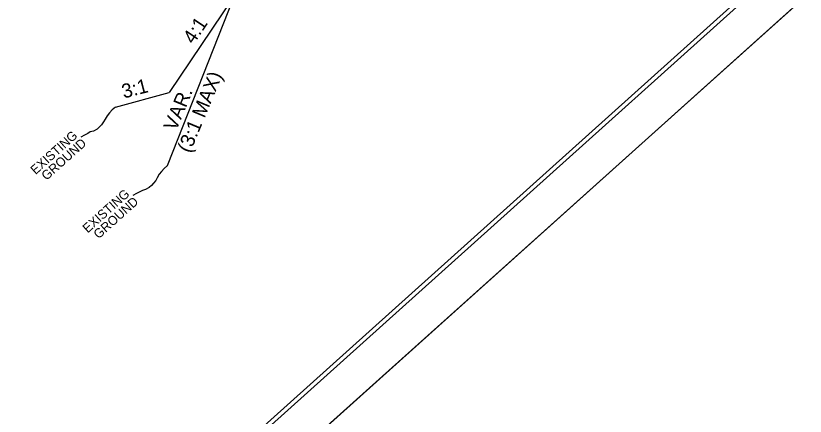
# Model space of a CAD drawing. Extents: x 2488411 to 2488707, y 383669 to 383962.
# Drawn here: x 2488587.3 to 2488643.1, y 383775.9 to 383804.2 of the extents above; entities that cross this region are included whole.
import ezdxf

# ---------------------------------------------------------------- set-up
doc = ezdxf.new("R2010")
doc.units = 0
for name, color, linetype in [('Old_Level_19', 7, 'Continuous'), ('Old_Level_21', 7, 'Continuous'), ('Prop Roadway Profile Bench Mark Info Text', 7, 'Continuous'), ('Prop XS SE Text', 7, 'Continuous'), ('Sheet Cutting Line CELL', 7, 'Continuous'), ('Sheet Plan CELL', 7, 'Continuous'), ('Sheet Title CELL', 7, 'Continuous'), ('Typical Text ID Circle CELL', 7, 'Continuous')]:
    doc.layers.add(name, color=color, linetype=linetype)

msp = doc.modelspace()

# ---------------------------------------------------------------- linework, layer by layer
at = {"layer": 'Old_Level_19'}
msp.add_lwpolyline([(2488619.231, 383961.604), (2488468.948, 383826.508), (2488557.194, 383728.341), (2488707.477, 383863.438)], close=True, dxfattribs=at)
at = {"layer": 'Old_Level_21'}
msp.add_lwpolyline([(2488620.631, 383959.24), (2488471.909, 383825.547), (2488556.553, 383731.388), (2488705.275, 383865.081)], close=True, dxfattribs=at)
at = {"layer": 'Prop XS SE Text'}
msp.add_line((2488557.194, 383728.341), (2488707.477, 383863.438), dxfattribs=at)
at = {"layer": 'Sheet Cutting Line CELL'}
msp.add_lwpolyline([(2488619.72, 383958.009), (2488485.857, 383837.674), (2488570.092, 383743.97), (2488703.955, 383864.305)], close=True, dxfattribs=at)
at = {"layer": 'Sheet Plan CELL'}
for p, q in [((2488598.022, 383793.579), (2488602.748, 383805.589)), ((2488602.748, 383805.589), (2488598.137, 383798.755)), ((2488594.343, 383797.711), (2488598.137, 383798.755))]:
    msp.add_line(p, q, dxfattribs=at)
at = {"layer": 'Typical Text ID Circle CELL'}
for points in [[(2488594.343, 383797.711), (2488594.111, 383797.509), (2488593.927, 383797.296), (2488593.755, 383797.095), (2488593.619, 383796.855), (2488593.51, 383796.663), (2488593.363, 383796.46), (2488593.205, 383796.295), (2488593.049, 383796.155), (2488592.795, 383796.02), (2488592.569, 383795.958), (2488592.389, 383795.844), (2488592.161, 383795.732), (2488591.906, 383795.597)], [(2488598.022, 383793.579), (2488597.791, 383793.378), (2488597.606, 383793.165), (2488597.434, 383792.964), (2488597.298, 383792.723), (2488597.189, 383792.531), (2488597.042, 383792.329), (2488596.885, 383792.164), (2488596.729, 383792.024), (2488596.474, 383791.889), (2488596.248, 383791.827), (2488596.069, 383791.713), (2488595.84, 383791.601), (2488595.585, 383791.466)]]:
    msp.add_lwpolyline(points, dxfattribs=at)

# ---------------------------------------------------------------- texts
at = {"layer": 'Prop Roadway Profile Bench Mark Info Text'}
for s, rotation, p in [('4:1', 55.9901, (2488599.862, 383802.1)), ('(3:1 MAX)', 67.4067, (2488599.608, 383794.413)), ('3:1', 14.5167, (2488594.932, 383798.314)), ('VAR. ', 67.4067, (2488598.628, 383795.971))]:
    msp.add_text(s, height=1, rotation=rotation, dxfattribs=at).set_placement(p)
at = {"layer": 'Sheet Title CELL'}
for s, p in [('EXISTING', (2488588.705, 383792.908)), ('GROUND', (2488589.477, 383792.494)), ('EXISTING', (2488592.384, 383788.777)), ('GROUND', (2488593.156, 383788.363))]:
    msp.add_text(s, height=0.65, rotation=41.9538, dxfattribs=at).set_placement(p)

doc.saveas('drawing.dxf')
